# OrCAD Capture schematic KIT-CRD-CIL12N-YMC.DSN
size Custom; title: KIT-CRD-CIL12N-YMC; rev: V1; company: Wolfspeed, A Cree Company; note: YM3 Six-Pack Evaluation Board Schematic; note: 535 W Research Center Blvd; note: Fayetteville, AR 72701
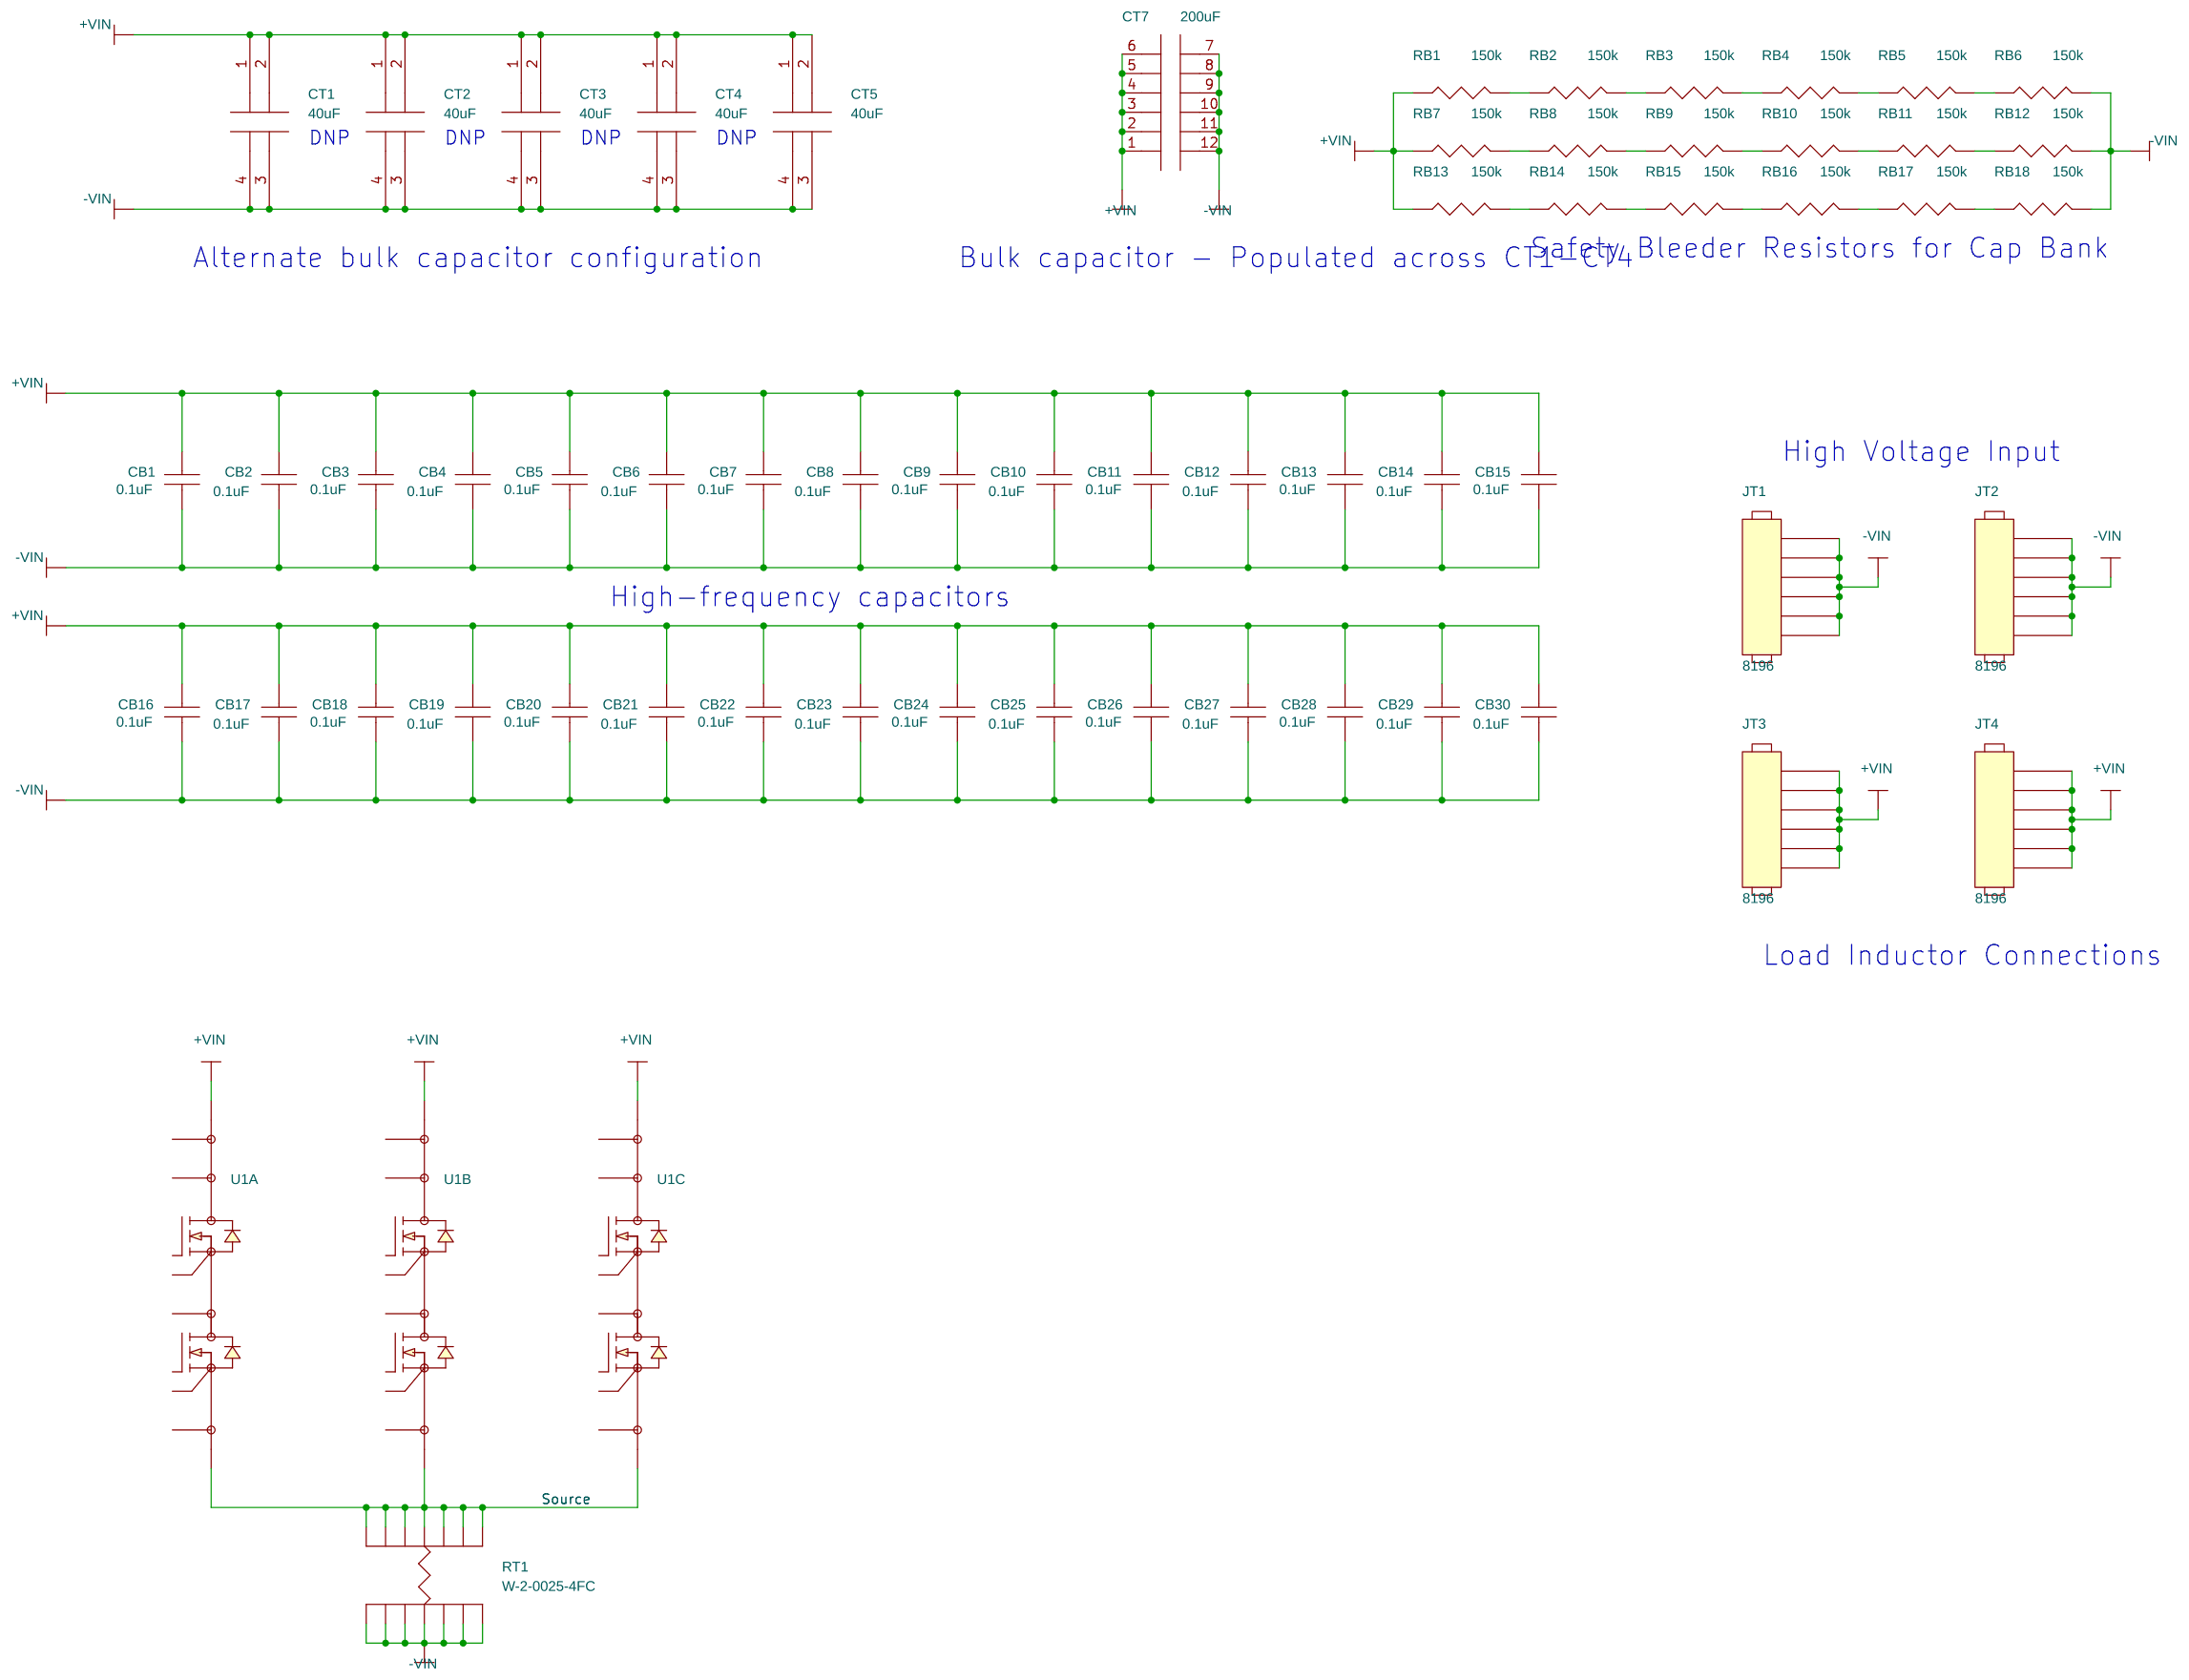
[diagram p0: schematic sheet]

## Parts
CB1  0.1uF  [B32672L]
CB2  0.1uF  [B32672L]
CB3  0.1uF  [B32672L]
CB4  0.1uF  [B32672L]
CB5  0.1uF  [B32672L]
CB6  0.1uF  [B32672L]
CB7  0.1uF  [B32672L]
CB8  0.1uF  [B32672L]
CB9  0.1uF  [B32672L]
CB10  0.1uF  [B32672L]
CB11  0.1uF  [B32672L]
CB12  0.1uF  [B32672L]
CB13  0.1uF  [B32672L]
CB14  0.1uF  [B32672L]
CB15  0.1uF  [B32672L]
CB16  0.1uF  [B32672L]
CB17  0.1uF  [B32672L]
CB18  0.1uF  [B32672L]
CB19  0.1uF  [B32672L]
CB20  0.1uF  [B32672L]
CB21  0.1uF  [B32672L]
CB22  0.1uF  [B32672L]
CB23  0.1uF  [B32672L]
CB24  0.1uF  [B32672L]
CB25  0.1uF  [B32672L]
CB26  0.1uF  [B32672L]
CB27  0.1uF  [B32672L]
CB28  0.1uF  [B32672L]
CB29  0.1uF  [B32672L]
CB30  0.1uF  [B32672L]
CT1  40uF  [B32778G]
CT2  40uF  [B32778G]
CT3  40uF  [B32778G]
CT4  40uF  [B32778G]
CT5  40uF  [B32778G]
CT7  200uF  [CDIP-12]
JT1  8196  [8196]
JT2  8196  [8196]
JT3  8196  [8196]
JT4  8196  [8196]
RB1  150k  [RESC6432X70N]
RB2  150k  [RESC6432X70N]
RB3  150k  [RESC6432X70N]
RB4  150k  [RESC6432X70N]
RB5  150k  [RESC6432X70N]
RB6  150k  [RESC6432X70N]
RB7  150k  [RESC6432X70N]
RB8  150k  [RESC6432X70N]
RB9  150k  [RESC6432X70N]
RB10  150k  [RESC6432X70N]
RB11  150k  [RESC6432X70N]
RB12  150k  [RESC6432X70N]
RB13  150k  [RESC6432X70N]
RB14  150k  [RESC6432X70N]
RB15  150k  [RESC6432X70N]
RB16  150k  [RESC6432X70N]
RB17  150k  [RESC6432X70N]
RB18  150k  [RESC6432X70N]
RT1  W-2-0025-4FC  [TM_CVR_W_14PIN_slots]
U1  HybridPack_PowerOnly  [HybridPack_PowerOnly]  (sections A,B,C)

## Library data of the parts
CB1-CB30 = CAP: CAP FILM 0.1UF 5% 1KVDC RADIAL; CLASS: DISCRETE; Company Part Status: New; Dielectric Type: Polypropylene (PP), Metallized; Manufacturer: EPCOS (TDK); Manufacturer PN: B32672L0104J000; PART_NUMBER: TMP-1585; Package Size: Radial; Rated Voltage: 1 kV; Tolerance: 5%
CT1-CT5 = buscap: CAP FILM 40UF 10% 1.1KVDC RADIAL; CLASS: DISCRETE; Company Part Status: New; Dielectric Type: Polypropylene (PP), Metallized; Manufacturer: EPCOS (TDK); Manufacturer PN: B32778G0406K000; PART_NUMBER: TMP-1584; Package Size: Radial; Rated Voltage: 1.1 kV; Tolerance: 10%
CT7 = CBUS-12: CAP FILM 200F 10% 1100VDC; CLASS: DISCRETE; Company Part Status: Released; Dielectric Type: Polypropylene (PP), Metallized; Manufacturer: EPCOS (TDK); Manufacturer PN: B32778J0207K000; PART_NUMBER: TMP-684; Package Size: 12-DIP; Tolerance: 10%
JT1-JT4 = Conn_Plug_6: TERMINAL SCREW PC HEAVY DUTY; CLASS: IO; Manufacturer: Keystone Electronics; PART_NUMBER: TMP-963
RB1-RB18 = R: RES SMD 220K OHM 1% 2W 2512; CLASS: DISCRETE; Manufacturer: TE Connectivity AMP Connectors; Manufacturer PN: 2176071-6; PART_NUMBER: TMP-659; Package Size: 2512 (6432 Metric); Rated Power: 2W; Temperature Coefficient: 100ppm/C; Tolerance: 1%
RT1 = W-2-0025-4FC
U1 = HybridPack_PowerOnly

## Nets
+Vin: CB1.1 CB2.1 CB3.1 CB4.1 CB5.1 CB6.1 CB7.1 CB8.1 CB9.1 CB10.1 CB11.1 CB12.1 CB13.1 CB14.1 CB15.1 CB16.1 CB17.1 CB18.1 CB19.1 CB20.1 CB21.1 CB22.1 CB23.1 CB24.1 CB25.1 CB26.1 CB27.1 CB28.1 CB29.1 CB30.1 CT1.1 CT1.2 CT2.1 CT2.2 CT3.1 CT3.2 CT4.1 CT4.2 CT5.1 CT5.2 CT7.1 CT7.2 CT7.3 CT7.4 CT7.5 CT7.6 JT3.1 JT3.2 JT3.3 JT3.4 JT3.5 JT3.6 JT4.1 JT4.2 JT4.3 JT4.4 JT4.5 JT4.6 RB1.1 RB7.1 RB13.1 U1.P1 U1.P2 U1.P3
-Vin: CB1.2 CB2.2 CB3.2 CB4.2 CB5.2 CB6.2 CB7.2 CB8.2 CB9.2 CB10.2 CB11.2 CB12.2 CB13.2 CB14.2 CB15.2 CB16.2 CB17.2 CB18.2 CB19.2 CB20.2 CB21.2 CB22.2 CB23.2 CB24.2 CB25.2 CB26.2 CB27.2 CB28.2 CB29.2 CB30.2 CT1.3 CT1.4 CT2.3 CT2.4 CT3.3 CT3.4 CT4.3 CT4.4 CT5.3 CT5.4 CT7.7 CT7.8 CT7.9 CT7.10 CT7.11 CT7.12 JT1.1 JT1.2 JT1.3 JT1.4 JT1.5 JT1.6 JT2.1 JT2.2 JT2.3 JT2.4 JT2.5 JT2.6 RB6.2 RB12.2 RB18.2 RT1.8 RT1.9 RT1.10 RT1.11 RT1.12 RT1.13 RT1.14
Source: RT1.1 RT1.2 RT1.3 RT1.4 RT1.5 RT1.6 RT1.7 U1.N1 U1.N2 U1.N3
N04994: RB1.2 RB2.1
N04998: RB2.2 RB3.1
N05002: RB3.2 RB4.1
N5310714: RB4.2 RB5.1
N5310720: RB5.2 RB6.1
N5311452: RB7.2 RB8.1
N5311456: RB8.2 RB9.1
N5311460: RB9.2 RB10.1
N5311464: RB10.2 RB11.1
N5311468: RB11.2 RB12.1
N5311692: RB13.2 RB14.1
N5311696: RB14.2 RB15.1
N5311700: RB15.2 RB16.1
N5311704: RB16.2 RB17.1
N5311708: RB17.2 RB18.1

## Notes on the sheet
- DNP
- DNP
- DNP
- DNP
- Alternate bulk capacitor configuration
- Bulk capacitor - Populated across CT1-CT4
- Safety Bleeder Resistors for Cap Bank
- High Voltage Input
- High-frequency capacitors
- Load Inductor Connections
